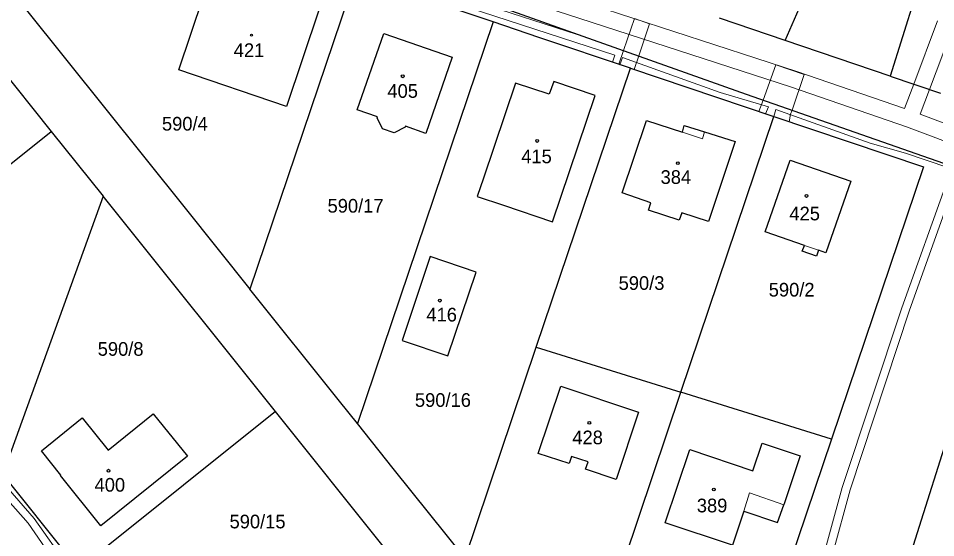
# Model space of a CAD drawing. Extents: x -701211 to -698780, y -1014269 to -1012378.
# Drawn here: x -700589 to -700475.1, y -1013402.8 to -1013338.3 of the extents above; entities that cross this region are included whole.
import ezdxf
from ezdxf.enums import TextEntityAlignment as Align

# ---------------------------------------------------------------- set-up
doc = ezdxf.new("R2010")
doc.units = 0
doc.header["$LTSCALE"] = 0.68
for name, color, linetype, lineweight in [('1', 7, 'Continuous', 25), ('13', 7, 'Continuous', 13), ('4', 7, 'Continuous', 13), ('5', 7, 'Continuous', 25)]:
    doc.layers.add(name, color=color, linetype=linetype, lineweight=lineweight)
doc.layers.add('2', color=7, linetype='Continuous')

msp = doc.modelspace()

# ---------------------------------------------------------------- linework, layer by layer
at = {"layer": '1'}
for p, q in [((-700493.76, -1013341.04), (-700487.37, -1013326.46)), ((-700602.61, -1013330.19), (-700584.87, -1013352.36)), ((-700475.79, -1013329.83), (-700480.72, -1013345.47)), ((-700569.04, -1013344.71), (-700565.07, -1013332.82)), ((-700547.08, -1013333), (-700560.22, -1013371.96)), ((-700530.02, -1013338.75), (-700541.39, -1013334.91)), ((-700530.87, -1013336.23), (-700498.58, -1013347.72)), ((-700588.12, -1013337.08), (-700568.26, -1013361.91)), ((-700551.67, -1013337.29), (-700555.67, -1013349.27)), ((-700493.76, -1013341.04), (-700501.91, -1013338.27)), ((-700530.02, -1013338.75), (-700546.87, -1013388.66)), ((-700524.34, -1013340.67), (-700530.02, -1013338.75)), ((-700546.88, -1013349.65), (-700543.6, -1013340.19)), ((-700543.6, -1013340.19), (-700535.1, -1013343.13)), ((-700512.96, -1013344.5), (-700524.34, -1013340.67)), ((-700480.72, -1013345.47), (-700493.76, -1013341.04)), ((-700535.1, -1013343.13), (-700538.35, -1013352.59)), ((-700555.67, -1013349.27), (-700569.04, -1013344.71)), ((-700524.66, -1013379.16), (-700512.96, -1013344.5)), ((-700512.96, -1013344.5), (-700495.15, -1013350.51)), ((-700480.72, -1013345.47), (-700474.45, -1013347.58)), ((-700527.24, -1013346.35), (-700531.22, -1013358.15)), ((-700523.04, -1013347.72), (-700527.24, -1013346.35)), ((-700522.47, -1013346.15), (-700523.04, -1013347.72)), ((-700517.33, -1013347.89), (-700522.47, -1013346.15)), ((-700498.58, -1013347.72), (-700463.95, -1013359.84)), ((-700522.62, -1013363.57), (-700517.33, -1013347.89)), ((-700544.35, -1013350.52), (-700546.88, -1013349.65)), ((-700544.4, -1013350.66), (-700544.35, -1013350.52)), ((-700543.73, -1013352.01), (-700544.4, -1013350.66)), ((-700506.69, -1013384.75), (-700495.15, -1013350.51)), ((-700542.31, -1013352.52), (-700543.73, -1013352.01)), ((-700540.95, -1013351.84), (-700542.31, -1013352.52)), ((-700540.9, -1013351.69), (-700540.95, -1013351.84)), ((-700538.35, -1013352.59), (-700540.9, -1013351.69)), ((-700506.49, -1013352.46), (-700506.28, -1013351.61)), ((-700506.28, -1013351.61), (-700503.78, -1013352.4)), ((-700613.35, -1013375.15), (-700584.87, -1013352.36)), ((-700584.87, -1013352.36), (-700578.44, -1013360.4)), ((-700503.78, -1013352.4), (-700499.94, -1013353.61)), ((-700499.94, -1013353.61), (-700503.27, -1013363.56)), ((-700496.22, -1013364.84), (-700493.15, -1013355.91)), ((-700493.15, -1013355.91), (-700485.61, -1013358.52)), ((-700531.22, -1013358.15), (-700531.98, -1013360.42)), ((-700485.61, -1013358.52), (-700488.69, -1013367.44)), ((-700510.43, -1013361.23), (-700513.99, -1013360)), ((-700483.38, -1013421.33), (-700463.95, -1013359.84)), ((-700578.44, -1013360.4), (-700590.9, -1013394.94)), ((-700576.78, -1013362.47), (-700578.44, -1013360.4)), ((-700531.98, -1013360.42), (-700528.72, -1013361.51)), ((-700510.71, -1013362.15), (-700510.43, -1013361.23)), ((-700557.02, -1013387.18), (-700576.78, -1013362.47)), ((-700568.26, -1013361.91), (-700560.22, -1013371.96)), ((-700528.72, -1013361.51), (-700522.62, -1013363.57)), ((-700506.93, -1013363.4), (-700510.71, -1013362.15)), ((-700506.58, -1013362.49), (-700506.93, -1013363.4)), ((-700503.27, -1013363.56), (-700506.58, -1013362.49)), ((-700491.37, -1013366.52), (-700496.22, -1013364.84)), ((-700491.62, -1013367.24), (-700491.37, -1013366.52)), ((-700489.62, -1013367.12), (-700489.87, -1013367.84)), ((-700488.69, -1013367.44), (-700489.62, -1013367.12)), ((-700537.81, -1013367.91), (-700541.3, -1013378.34)), ((-700532.11, -1013369.85), (-700537.81, -1013367.91)), ((-700489.87, -1013367.84), (-700491.62, -1013367.24)), ((-700535.62, -1013380.25), (-700532.11, -1013369.85)), ((-700549.09, -1013385.88), (-700560.22, -1013371.96)), ((-700541.3, -1013378.34), (-700535.62, -1013380.25)), ((-700533.5, -1013405.37), (-700524.66, -1013379.16)), ((-700524.66, -1013379.16), (-700506.69, -1013384.75)), ((-700524.4, -1013392.37), (-700521.6, -1013384)), ((-700521.6, -1013384), (-700511.96, -1013387.23)), ((-700518.44, -1013419.59), (-700506.69, -1013384.75)), ((-700487.99, -1013390.58), (-700506.69, -1013384.75)), ((-700546.87, -1013388.66), (-700549.09, -1013385.88)), ((-700557.02, -1013387.18), (-700581.46, -1013406.73)), ((-700577.82, -1013391.96), (-700572.21, -1013387.44)), ((-700572.21, -1013387.44), (-700567.95, -1013392.73)), ((-700543.65, -1013403.89), (-700557.02, -1013387.18)), ((-700511.96, -1013387.23), (-700514.73, -1013395.61)), ((-700586.11, -1013392.04), (-700581.04, -1013387.96)), ((-700581.04, -1013387.96), (-700577.82, -1013391.96)), ((-700542.41, -1013394.23), (-700546.87, -1013388.66)), ((-700497.75, -1013394.53), (-700496.59, -1013391.08)), ((-700496.59, -1013391.08), (-700491.87, -1013392.69)), ((-700583.67, -1013395.07), (-700586.11, -1013392.04)), ((-700508.65, -1013401), (-700505.58, -1013391.9)), ((-700505.58, -1013391.9), (-700497.75, -1013394.53)), ((-700567.95, -1013392.73), (-700578.73, -1013401.37)), ((-700520.59, -1013393.64), (-700524.4, -1013392.37)), ((-700520.29, -1013392.74), (-700520.59, -1013393.64)), ((-700518.23, -1013393.43), (-700520.29, -1013392.74)), ((-700491.87, -1013392.69), (-700493.93, -1013398.75)), ((-700533.5, -1013405.37), (-700542.41, -1013394.23)), ((-700518.53, -1013394.33), (-700518.23, -1013393.43)), ((-700514.73, -1013395.61), (-700518.53, -1013394.33)), ((-700581.46, -1013406.73), (-700590.9, -1013394.94)), ((-700583.75, -1013395.13), (-700583.67, -1013395.07)), ((-700578.73, -1013401.37), (-700583.75, -1013395.13)), ((-700494.69, -1013400.97), (-700493.93, -1013398.75)), ((-700498.9, -1013399.53), (-700500.27, -1013403.77)), ((-700498.9, -1013399.53), (-700494.69, -1013400.97)), ((-700500.27, -1013403.77), (-700508.65, -1013401))]:
    msp.add_line(p, q, dxfattribs=at)
for points in [[(-700513.99, -1013360), (-700510.98, -1013350.99), (-700506.49, -1013352.46)], [(-700495.15, -1013350.51), (-700476.58, -1013356.76), (-700487.99, -1013390.58)], [(-700487.99, -1013390.58), (-700498.46, -1013421.65), (-700507.35, -1013423.32)]]:
    msp.add_lwpolyline(points, dxfattribs=at)
at = {"layer": '13'}
for points in [[(-700556.41, -1013261.59), (-700570.13, -1013302.02), (-700574.19, -1013314.19), (-700575.89, -1013319.29), (-700569.54, -1013321.33), (-700543.46, -1013330.11), (-700531.04, -1013334.56), (-700528.72, -1013335.19), (-700519.37, -1013338.26), (-700492.98, -1013346.86), (-700478.67, -1013351.78), (-700454.55, -1013360.87)], [(-700474.84, -1013338.62), (-700477.78, -1013346.46), (-700478.93, -1013349.51), (-700492.32, -1013344.9), (-700517.76, -1013336.61), (-700516.63, -1013333.27), (-700518.55, -1013332.62), (-700519.69, -1013335.98), (-700527.15, -1013333.54), (-700526.12, -1013330.09), (-700521.06, -1013313.1), (-700519.28, -1013306.98), (-700517.75, -1013307.45), (-700517.17, -1013305.5), (-700518.69, -1013305.03), (-700511.51, -1013282.1)], [(-700492.28, -1013420.99), (-700485.7, -1013396.89), (-700478.3, -1013374.57), (-700472.55, -1013358.45), (-700472.31, -1013356.91), (-700492.9, -1013349.71), (-700498.58, -1013347.72), (-700518.18, -1013340.75), (-700533.29, -1013335.83), (-700542.3, -1013332.67), (-700557.49, -1013327.67), (-700570.93, -1013322.78)], [(-700533.11, -1013336.94), (-700514.91, -1013342.86), (-700515.21, -1013343.74), (-700514.41, -1013344.01), (-700514.26, -1013344.06), (-700513.96, -1013343.18), (-700501.81, -1013347.51), (-700495.84, -1013349.3), (-700496.18, -1013350.16), (-700495.15, -1013350.51), (-700494.89, -1013349.61), (-700483.18, -1013353.83), (-700478.8, -1013355.05), (-700473.56, -1013356.83)], [(-700452.93, -1013359.28), (-700476.99, -1013350.21), (-700475.83, -1013347.12), (-700473.24, -1013340.23)], [(-700473.53, -1013358.21), (-700479.26, -1013374.29), (-700486.66, -1013396.61), (-700493.2, -1013420.57)], [(-700582.92, -1013406.24), (-700586.98, -1013400.44), (-700590.28, -1013396.71), (-700589.88, -1013396.21), (-700590.52, -1013395.41), (-700591.03, -1013396.04), (-700592.77, -1013394.83), (-700596.08, -1013393.59), (-700598.59, -1013393.26), (-700599.66, -1013393.82), (-700601.27, -1013395.63), (-700604.72, -1013397.58), (-700610.34, -1013401.88), (-700610.61, -1013401.6), (-700611.4, -1013402.24), (-700610.91, -1013402.73), (-700611.13, -1013404.55)], [(-700609.92, -1013402.81), (-700604.16, -1013398.42), (-700600.63, -1013396.41), (-700599.04, -1013394.62), (-700598.43, -1013394.3), (-700596.32, -1013394.57), (-700593.27, -1013395.73), (-700591.26, -1013397.11), (-700587.76, -1013401.06), (-700583.99, -1013406.51)]]:
    msp.add_lwpolyline(points, dxfattribs=at)
for points in [[(-700512.47, -1013338.32), (-700513.83, -1013342.3), (-700514.41, -1013344.01), (-700512.96, -1013344.5), (-700512.52, -1013344.65), (-700511.94, -1013342.96), (-700510.58, -1013338.97)], [(-700494.91, -1013344.07), (-700496.5, -1013348.45), (-700497.02, -1013349.88), (-700495.15, -1013350.51), (-700493.24, -1013351.15), (-700493.07, -1013350.21), (-700492.9, -1013349.71), (-700491.38, -1013345.26)]]:
    msp.add_lwpolyline(points, close=True, dxfattribs=at)
at = {"layer": '4'}
for p, q in [((-700506.49, -1013352.46), (-700504.03, -1013353.27)), ((-700504.03, -1013353.27), (-700503.78, -1013352.4)), ((-700489.62, -1013367.12), (-700491.37, -1013366.52)), ((-700498.9, -1013399.53), (-700498.18, -1013397.29)), ((-700498.18, -1013397.29), (-700493.93, -1013398.75))]:
    msp.add_line(p, q, dxfattribs=at)
at = {"layer": '5'}
for centre, radius in [((-700560.0046, -1013340.3994), 0.1172), ((-700541.2368, -1013345.4992), 0.175), ((-700524.5368, -1013353.5392), 0.175), ((-700507.0868, -1013356.2992), 0.175), ((-700491.0968, -1013360.3692), 0.175), ((-700536.6368, -1013373.3792), 0.175), ((-700518.0668, -1013388.5792), 0.175), ((-700577.7668, -1013394.5192), 0.175), ((-700502.5968, -1013396.8492), 0.175)]:
    msp.add_circle(centre, radius, dxfattribs=at)

# ---------------------------------------------------------------- texts
at = {"layer": '2'}
for s, p in [('421', (-700562.22, -1013343.105)), ('405', (-700543.14, -1013348.175)), ('590/4', (-700571.13, -1013352.245)), ('415', (-700526.52, -1013356.305)), ('384', (-700509.22, -1013358.875)), ('590/17', (-700550.57, -1013362.445)), ('590/3', (-700514.43, -1013372.045)), ('590/2', (-700495.79, -1013372.875)), ('416', (-700538.3, -1013375.975)), ('590/8', (-700579.11, -1013380.235)), ('590/16', (-700539.72, -1013386.585)), ('428', (-700520.18, -1013391.235)), ('400', (-700579.5, -1013397.125)), ('389', (-700504.72, -1013399.695)), ('590/15', (-700562.74, -1013401.685))]:
    msp.add_text(s, height=1.7, dxfattribs=at).set_placement(p)
msp.add_text('425', height=1.7, dxfattribs=at).set_placement((-700491.329, -1013363.405), align=Align.CENTER)

doc.saveas('drawing.dxf')
